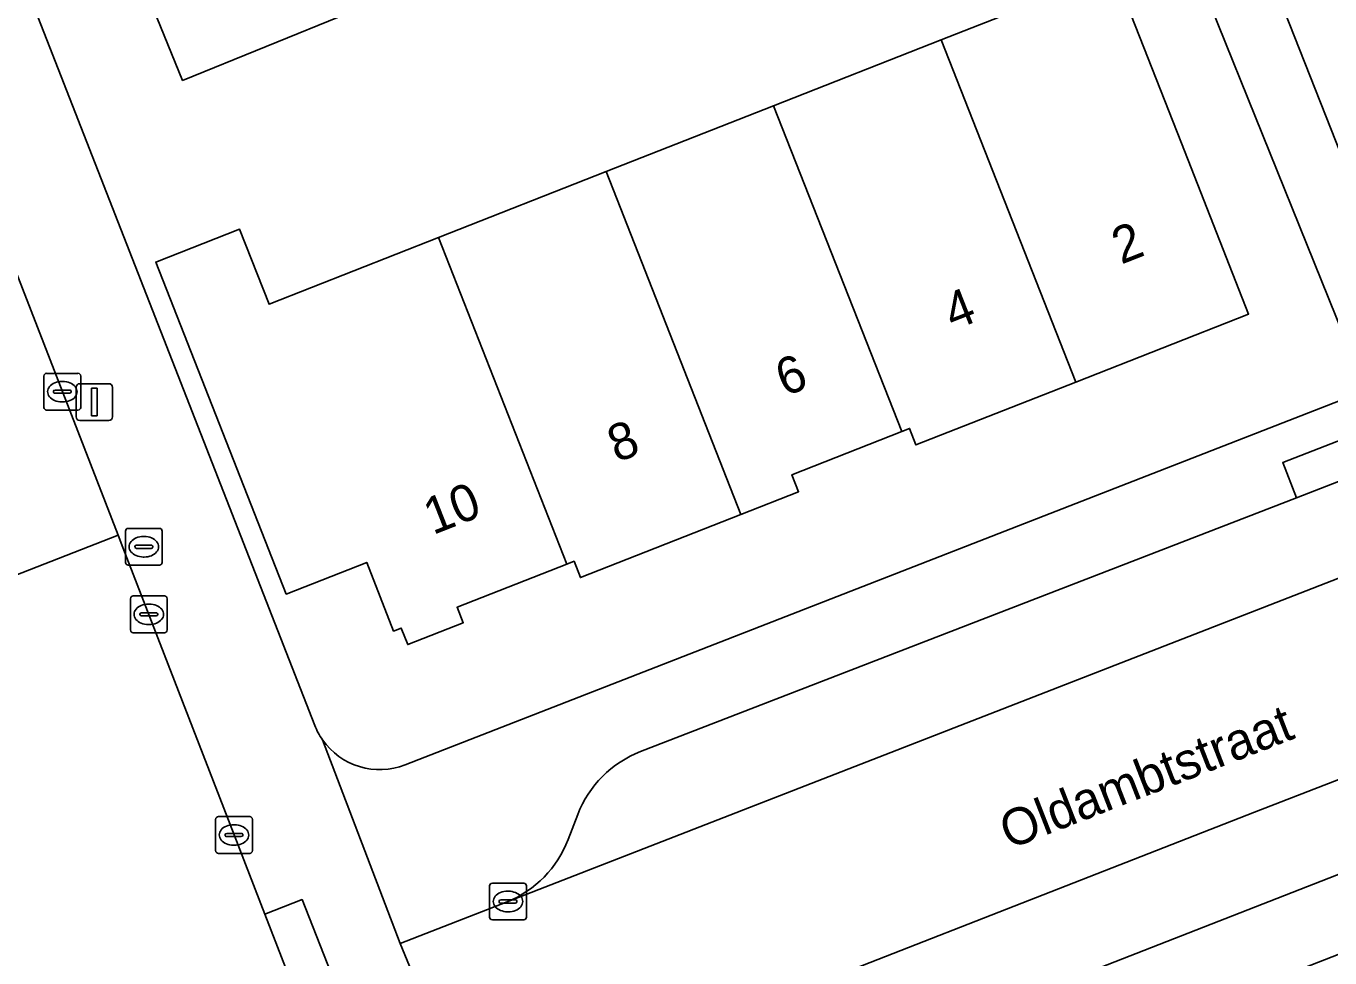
# Model space of a CAD drawing. Extents: x 159680 to 160786, y 387323 to 388340.
# Drawn here: x 159913.35 to 159948.85, y 387801.26 to 387826.64 of the extents above; entities that cross this region are included whole.
import ezdxf

# ---------------------------------------------------------------- set-up
doc = ezdxf.new("R2010")
doc.units = 0
for name, color, linetype in [('IMGEO_Brandkraan', 7, 'Continuous'), ('IMGEO_Erf', 7, 'Continuous'), ('IMGEO_Kolk', 7, 'Continuous'), ('IMGEO_Lichtmast', 7, 'Continuous'), ('IMGEO_Openbare_ruimte_label', 7, 'Continuous'), ('IMGEO_Pand', 7, 'Continuous'), ('IMGEO_Pand_nummerreeks', 7, 'Continuous'), ('IMGEO_Parkeervlak_open', 7, 'Continuous'), ('IMGEO_Rijbaan_lokaal_gesloten', 7, 'Continuous'), ('IMGEO_Rijbaan_lokaal_open', 7, 'Continuous'), ('IMGEO_Voetpad_open', 7, 'Continuous')]:
    doc.layers.add(name, color=color, linetype=linetype)

msp = doc.modelspace()

# ---------------------------------------------------------------- linework, layer by layer
at = {"layer": 'IMGEO_Brandkraan'}
for p, q in [((159916.053, 387812.033), (159916.053, 387812.885)), ((159916.128, 387812.959), (159916.98, 387812.959)), ((159917.054, 387812.885), (159917.054, 387812.033)), ((159916.541, 387812.739), (159916.566, 387812.739)), ((159916.312, 387812.453), (159916.312, 387812.465)), ((159916.75, 387812.416), (159916.352, 387812.416)), ((159916.355, 387812.502), (159916.753, 387812.502)), ((159916.564, 387812.179), (159916.539, 387812.179)), ((159916.796, 387812.465), (159916.796, 387812.453)), ((159916.98, 387811.959), (159916.128, 387811.959))]:
    msp.add_line(p, q, dxfattribs=at)
for points in [[(159916.053, 387812.033), (159916.053, 387812.885)], [(159916.128, 387812.959), (159916.98, 387812.959)], [(159917.054, 387812.885), (159917.054, 387812.033)], [(159916.98, 387811.959), (159916.128, 387811.959)]]:
    msp.add_lwpolyline(points, dxfattribs=at)
for centre, radius, start, end in [((159916.13, 387812.883), 0.0765, 91.552, 178.448), ((159916.13, 387812.883), 0.0765, 91.552, 178.448), ((159916.978, 387812.883), 0.0765, 1.552, 88.448), ((159916.978, 387812.883), 0.0765, 1.552, 88.448), ((159916.352, 387812.462), 0.0403, 85.8775, 175.7526), ((159916.349, 387812.452), 0.0366, 178.938, 274.7102), ((159916.753, 387812.459), 0.043, 264.8664, 352.4533), ((159916.757, 387812.464), 0.0386, 1.7309, 96.639), ((159916.13, 387812.035), 0.0765, 181.552, 268.448), ((159916.13, 387812.035), 0.0765, 181.552, 268.448), ((159916.978, 387812.035), 0.0765, 271.552, 358.448), ((159916.978, 387812.035), 0.0765, 271.552, 358.448)]:
    msp.add_arc(centre, radius, start, end, dxfattribs=at)
for centre, major_axis, ratio, start_param, end_param in [((159916.54, 387812.459), (-0.387, 0.002), 0.722429, 4.712389, 7.853982), ((159916.565, 387812.459), (-0.39, 0.002), 0.717154, 1.570796, 4.712389)]:
    msp.add_ellipse(centre, major_axis=major_axis, ratio=ratio, start_param=start_param, end_param=end_param, dxfattribs=at)
at = {"layer": 'IMGEO_Erf'}
for points in [[(159966.687, 387844.688), (159952.097, 387882.134), (159929.514, 387872.862), (159951.443, 387817.344), (159972.219, 387825.439)], [(159944.202, 387830.659), (159941.502, 387829.654), (159939.753, 387834.352), (159935.731, 387832.856), (159934.772, 387835.434), (159923.434, 387831.171), (159924.707, 387828.045), (159922.162, 387827.009), (159917.609, 387825.155), (159916.31, 387828.346), (159913.522, 387827.256), (159921.209, 387807.595)], [(159923.671, 387806.523), (159949.825, 387816.714), (159944.202, 387830.659)], [(159930.956, 387791.493), (159935.682, 387793.345), (159940.268, 387795.143), (159944.684, 387796.874), (159944.864, 387796.414), (159945.036, 387796.481), (159948.051, 387797.663), (159947.883, 387798.09), (159949.328, 387798.656), (159949.51, 387798.191), (159949.638, 387798.241), (159952.595, 387799.4), (159952.41, 387799.873), (159953.833, 387800.43), (159954.003, 387799.998), (159954.351, 387800.134), (159953.242, 387802.979), (159928.783, 387793.44)]]:
    msp.add_lwpolyline(points, dxfattribs=at)
msp.add_lwpolyline([(159938.267, 387826.262), (159942.97, 387828.112), (159944.804, 387823.448), (159946.634, 387818.794), (159941.93, 387816.944), (159937.577, 387815.233), (159937.402, 387815.68), (159937.188, 387815.596), (159934.2, 387814.421), (159934.382, 387813.956), (159932.807, 387813.337), (159928.442, 387811.62), (159928.267, 387812.065), (159928.068, 387811.987), (159925.085, 387810.814), (159925.251, 387810.392), (159923.738, 387809.797), (159923.562, 387810.247), (159923.355, 387810.165), (159922.621, 387812.031), (159920.432, 387811.17), (159916.878, 387820.209), (159919.159, 387821.106), (159919.962, 387819.064), (159924.573, 387820.877), (159929.138, 387822.672), (159933.702, 387824.467)], close=True, dxfattribs=at)
for centre, radius, start, end in [((159922.971, 387808.288), 1.893, 201.4763, 214.8972), ((159922.976, 387808.289), 1.898, 214.8319, 291.4852)]:
    msp.add_arc(centre, radius, start, end, dxfattribs=at)
at = {"layer": 'IMGEO_Kolk'}
for p, q in [((159913.908, 387817.181), (159914.76, 387817.181)), ((159913.833, 387816.255), (159913.833, 387817.107)), ((159914.321, 387816.961), (159914.346, 387816.961)), ((159914.834, 387817.107), (159914.834, 387816.255)), ((159914.092, 387816.675), (159914.092, 387816.687)), ((159914.53, 387816.638), (159914.132, 387816.638)), ((159914.135, 387816.724), (159914.533, 387816.724)), ((159914.576, 387816.687), (159914.576, 387816.675)), ((159914.76, 387816.181), (159913.908, 387816.181)), ((159914.344, 387816.401), (159914.319, 387816.401)), ((159916.264, 387811.12), (159917.116, 387811.12)), ((159916.189, 387810.194), (159916.189, 387811.046)), ((159916.677, 387810.9), (159916.702, 387810.9)), ((159917.19, 387811.046), (159917.19, 387810.194)), ((159916.448, 387810.614), (159916.448, 387810.626)), ((159916.886, 387810.577), (159916.488, 387810.577)), ((159916.491, 387810.663), (159916.889, 387810.663)), ((159916.932, 387810.626), (159916.932, 387810.614)), ((159917.116, 387810.12), (159916.264, 387810.12)), ((159916.7, 387810.34), (159916.675, 387810.34)), ((159918.584, 387805.112), (159919.436, 387805.112)), ((159918.509, 387804.186), (159918.509, 387805.038)), ((159918.997, 387804.892), (159919.022, 387804.892)), ((159919.51, 387805.038), (159919.51, 387804.186)), ((159918.768, 387804.606), (159918.768, 387804.618)), ((159919.206, 387804.569), (159918.808, 387804.569)), ((159918.811, 387804.655), (159919.209, 387804.655)), ((159919.252, 387804.618), (159919.252, 387804.606)), ((159919.436, 387804.112), (159918.584, 387804.112)), ((159919.02, 387804.332), (159918.995, 387804.332)), ((159926.044, 387803.301), (159926.896, 387803.301)), ((159925.969, 387802.375), (159925.969, 387803.227)), ((159926.457, 387803.081), (159926.482, 387803.081)), ((159926.97, 387803.227), (159926.97, 387802.375)), ((159926.228, 387802.795), (159926.228, 387802.807)), ((159926.666, 387802.758), (159926.268, 387802.758)), ((159926.271, 387802.844), (159926.669, 387802.844)), ((159926.712, 387802.807), (159926.712, 387802.795)), ((159926.896, 387802.301), (159926.044, 387802.301)), ((159926.48, 387802.521), (159926.455, 387802.521))]:
    msp.add_line(p, q, dxfattribs=at)
for points in [[(159913.908, 387817.181), (159914.76, 387817.181)], [(159913.833, 387816.255), (159913.833, 387817.107)], [(159914.834, 387817.107), (159914.834, 387816.255)], [(159914.76, 387816.181), (159913.908, 387816.181)], [(159916.264, 387811.12), (159917.116, 387811.12)], [(159916.189, 387810.194), (159916.189, 387811.046)], [(159917.19, 387811.046), (159917.19, 387810.194)], [(159917.116, 387810.12), (159916.264, 387810.12)], [(159918.584, 387805.112), (159919.436, 387805.112)], [(159918.509, 387804.186), (159918.509, 387805.038)], [(159919.51, 387805.038), (159919.51, 387804.186)], [(159919.436, 387804.112), (159918.584, 387804.112)], [(159926.044, 387803.301), (159926.896, 387803.301)], [(159925.969, 387802.375), (159925.969, 387803.227)], [(159926.97, 387803.227), (159926.97, 387802.375)], [(159926.896, 387802.301), (159926.044, 387802.301)]]:
    msp.add_lwpolyline(points, dxfattribs=at)
for centre, radius, start, end in [((159913.91, 387817.105), 0.0765, 91.552, 178.448), ((159913.91, 387817.105), 0.0765, 91.552, 178.448), ((159914.758, 387817.105), 0.0765, 1.552, 88.448), ((159914.758, 387817.105), 0.0765, 1.552, 88.448), ((159914.132, 387816.684), 0.0403, 85.8775, 175.7526), ((159914.129, 387816.674), 0.0366, 178.938, 274.7102), ((159914.533, 387816.681), 0.043, 264.8664, 352.4533), ((159914.537, 387816.686), 0.0386, 1.7309, 96.639), ((159913.91, 387816.257), 0.0765, 181.552, 268.448), ((159913.91, 387816.257), 0.0765, 181.552, 268.448), ((159914.758, 387816.257), 0.0765, 271.552, 358.448), ((159914.758, 387816.257), 0.0765, 271.552, 358.448), ((159916.266, 387811.044), 0.0765, 91.552, 178.448), ((159916.266, 387811.044), 0.0765, 91.552, 178.448), ((159917.114, 387811.044), 0.0765, 1.552, 88.448), ((159917.114, 387811.044), 0.0765, 1.552, 88.448), ((159916.488, 387810.623), 0.0403, 85.8775, 175.7526), ((159916.485, 387810.613), 0.0366, 178.938, 274.7102), ((159916.889, 387810.62), 0.043, 264.8664, 352.4533), ((159916.893, 387810.625), 0.0386, 1.7309, 96.639), ((159916.266, 387810.196), 0.0765, 181.552, 268.448), ((159916.266, 387810.196), 0.0765, 181.552, 268.448), ((159917.114, 387810.196), 0.0765, 271.552, 358.448), ((159917.114, 387810.196), 0.0765, 271.552, 358.448), ((159918.586, 387805.036), 0.0765, 91.552, 178.448), ((159918.586, 387805.036), 0.0765, 91.552, 178.448), ((159919.434, 387805.036), 0.0765, 1.552, 88.448), ((159919.434, 387805.036), 0.0765, 1.552, 88.448), ((159918.808, 387804.615), 0.0403, 85.8775, 175.7526), ((159918.805, 387804.605), 0.0366, 178.938, 274.7102), ((159919.209, 387804.612), 0.043, 264.8664, 352.4533), ((159919.213, 387804.617), 0.0386, 1.7309, 96.639), ((159918.586, 387804.188), 0.0765, 181.552, 268.448), ((159918.586, 387804.188), 0.0765, 181.552, 268.448), ((159919.434, 387804.188), 0.0765, 271.552, 358.448), ((159919.434, 387804.188), 0.0765, 271.552, 358.448), ((159926.046, 387803.225), 0.0765, 91.552, 178.448), ((159926.046, 387803.225), 0.0765, 91.552, 178.448), ((159926.894, 387803.225), 0.0765, 1.552, 88.448), ((159926.894, 387803.225), 0.0765, 1.552, 88.448), ((159926.268, 387802.804), 0.0403, 85.8775, 175.7526), ((159926.265, 387802.794), 0.0366, 178.938, 274.7102), ((159926.669, 387802.801), 0.043, 264.8664, 352.4533), ((159926.673, 387802.806), 0.0386, 1.7309, 96.639), ((159926.046, 387802.377), 0.0765, 181.552, 268.448), ((159926.046, 387802.377), 0.0765, 181.552, 268.448), ((159926.894, 387802.377), 0.0765, 271.552, 358.448), ((159926.894, 387802.377), 0.0765, 271.552, 358.448)]:
    msp.add_arc(centre, radius, start, end, dxfattribs=at)
for centre, major_axis, ratio, start_param, end_param in [((159914.32, 387816.681), (-0.387, 0.002), 0.722429, 4.712389, 7.853982), ((159914.345, 387816.681), (-0.39, 0.002), 0.717154, 1.570796, 4.712389), ((159916.676, 387810.62), (-0.387, 0.002), 0.722429, 4.712389, 7.853982), ((159916.701, 387810.62), (-0.39, 0.002), 0.717154, 1.570796, 4.712389), ((159918.996, 387804.612), (-0.387, 0.002), 0.722429, 4.712389, 7.853982), ((159919.021, 387804.612), (-0.39, 0.002), 0.717154, 1.570796, 4.712389), ((159926.456, 387802.801), (-0.387, 0.002), 0.722429, 4.712389, 7.853982), ((159926.481, 387802.801), (-0.39, 0.002), 0.717154, 1.570796, 4.712389)]:
    msp.add_ellipse(centre, major_axis=major_axis, ratio=ratio, start_param=start_param, end_param=end_param, dxfattribs=at)
at = {"layer": 'IMGEO_Lichtmast'}
for p, q in [((159914.709, 387815.999), (159914.709, 387816.799)), ((159914.709, 387816.799), (159914.709, 387815.999)), ((159914.809, 387816.899), (159915.599, 387816.899)), ((159915.599, 387816.899), (159914.809, 387816.899)), ((159915.699, 387816.799), (159915.699, 387815.999)), ((159915.699, 387815.999), (159915.699, 387816.799)), ((159915.599, 387815.899), (159914.809, 387815.899)), ((159914.809, 387815.899), (159915.599, 387815.899))]:
    msp.add_line(p, q, dxfattribs=at)
msp.add_lwpolyline([(159915.129, 387816.774), (159915.279, 387816.774), (159915.279, 387816.024), (159915.129, 387816.024), (159915.129, 387816.774)], dxfattribs=at)
for centre, start, end in [((159914.809, 387816.799), 90, 180), ((159914.809, 387816.799), 90, 180), ((159915.599, 387816.799), 0, 90), ((159915.599, 387816.799), 360, 90), ((159914.809, 387815.999), 180, 270), ((159914.809, 387815.999), 180, 270), ((159915.599, 387815.999), 270, 0), ((159915.599, 387815.999), 270, 0)]:
    msp.add_arc(centre, 0.1, start, end, dxfattribs=at)
at = {"layer": 'IMGEO_Pand'}
for points in [[(159920.902, 387830.216), (159916.31, 387828.346), (159917.609, 387825.155), (159922.162, 387827.009)], [(159941.93, 387816.944), (159946.634, 387818.794), (159944.804, 387823.448), (159942.97, 387828.112), (159938.267, 387826.262)], [(159938.267, 387826.262), (159933.702, 387824.467), (159937.188, 387815.596), (159937.402, 387815.68), (159937.577, 387815.233), (159941.93, 387816.944)], [(159933.702, 387824.467), (159929.138, 387822.672), (159932.807, 387813.337), (159934.382, 387813.956), (159934.2, 387814.421), (159937.188, 387815.596)], [(159928.068, 387811.987), (159928.267, 387812.065), (159928.442, 387811.62), (159932.807, 387813.337), (159929.138, 387822.672), (159924.573, 387820.877)], [(159924.573, 387820.877), (159919.962, 387819.064), (159919.159, 387821.106), (159916.878, 387820.209), (159920.432, 387811.17), (159922.621, 387812.031), (159923.355, 387810.165), (159923.562, 387810.247), (159923.738, 387809.797), (159925.251, 387810.392), (159925.085, 387810.814), (159928.068, 387811.987)]]:
    msp.add_lwpolyline(points, close=True, dxfattribs=at)
at = {"layer": 'IMGEO_Parkeervlak_open'}
for points in [[(159966.707, 387821.058), (159951.326, 387815.106), (159947.936, 387813.795), (159930.079, 387806.885)], [(159926.446, 387802.791), (159949.224, 387811.657), (159970.967, 387820.07)], [(159972.771, 387815.3), (159946.794, 387805.237), (159929.996, 387798.667)], [(159934.755, 387797.935), (159969.917, 387811.687)], [(159928.368, 387805.17), (159928.104, 387804.485)]]:
    msp.add_lwpolyline(points, dxfattribs=at)
for centre, start, end in [((159931.168, 387804.088), 111.266, 158.8678), ((159925.305, 387805.566), 292.3524, 338.8782)]:
    msp.add_arc(centre, 3.001, start, end, dxfattribs=at)
at = {"layer": 'IMGEO_Rijbaan_lokaal_gesloten'}
msp.add_lwpolyline([(159911.857, 387804.088), (159909.597, 387810.335), (159915.853, 387812.774), (159911.972, 387822.765)], dxfattribs=at)
at = {"layer": 'IMGEO_Rijbaan_lokaal_open'}
for points in [[(159972.771, 387815.3), (159974.926, 387816.135), (159976.607, 387816.786), (159974.995, 387821.629), (159970.967, 387820.07), (159949.224, 387811.657), (159926.446, 387802.791), (159923.532, 387801.657), (159925.493, 387796.906), (159929.996, 387798.667), (159946.794, 387805.237)], [(159919.846, 387802.456), (159919.01, 387804.612), (159915.983, 387812.438), (159915.853, 387812.774), (159909.597, 387810.335), (159911.857, 387804.088), (159912.558, 387802.402), (159914.429, 387797.56), (159919.835, 387783.57), (159921.528, 387779.204), (159927.881, 387781.717), (159926.227, 387785.997), (159923.212, 387793.775)]]:
    msp.add_lwpolyline(points, close=True, dxfattribs=at)
at = {"layer": 'IMGEO_Voetpad_open'}
for points in [[(159888.928, 387881.56), (159894.152, 387868.64), (159895.931, 387864.06), (159896.928, 387864.448), (159898.216, 387861.134), (159897.219, 387860.746), (159906.532, 387836.771), (159907.513, 387834.245), (159910.633, 387826.211), (159911.615, 387826.638), (159912.965, 387823.164), (159911.972, 387822.765), (159915.853, 387812.774), (159915.983, 387812.438), (159919.01, 387804.612), (159919.846, 387802.456), (159920.861, 387802.854), (159924.268, 387794.188), (159923.212, 387793.775), (159926.227, 387785.997)], [(159921.209, 387807.595), (159913.522, 387827.256), (159912.952, 387828.714), (159900.404, 387860.81), (159899.864, 387862.192), (159898.601, 387865.422), (159892.901, 387880.003)], [(159944.202, 387830.659), (159949.825, 387816.714), (159951.443, 387817.344), (159929.514, 387872.862)], [(159972.219, 387825.439), (159951.443, 387817.344), (159949.825, 387816.714), (159923.671, 387806.523)], [(159930.079, 387806.885), (159947.936, 387813.795), (159947.564, 387814.756), (159950.954, 387816.067), (159951.326, 387815.106), (159966.707, 387821.058)], [(159969.917, 387811.687), (159934.755, 387797.935)], [(159921.418, 387807.205), (159923.532, 387801.657), (159926.446, 387802.791)], [(159927.592, 387791.332), (159925.493, 387796.906), (159923.532, 387801.657), (159921.418, 387807.205)], [(159928.104, 387804.485), (159928.368, 387805.17)], [(159928.783, 387793.44), (159953.242, 387802.979)]]:
    msp.add_lwpolyline(points, dxfattribs=at)
for points in [[(159951.326, 387815.106), (159950.954, 387816.067), (159947.564, 387814.756), (159947.936, 387813.795)], [(159920.861, 387802.854), (159919.846, 387802.456), (159923.212, 387793.775), (159924.268, 387794.188)]]:
    msp.add_lwpolyline(points, close=True, dxfattribs=at)
for centre, radius, start, end in [((159922.971, 387808.288), 1.893, 201.4763, 214.8972), ((159922.976, 387808.289), 1.898, 214.8319, 291.4852), ((159931.168, 387804.088), 3.001, 111.266, 158.8678), ((159925.305, 387805.566), 3.001, 292.3524, 338.8782)]:
    msp.add_arc(centre, radius, start, end, dxfattribs=at)

# ---------------------------------------------------------------- texts
at = {"layer": 'IMGEO_Openbare_ruimte_label'}
msp.add_text('Oldambtstraat', height=1, rotation=21.2802, dxfattribs=at).set_placement((159940.11, 387804.212))
at = {"layer": 'IMGEO_Pand_nummerreeks'}
for s, p in [('2', (159943.164, 387820.138)), ('4', (159938.587, 387818.34)), ('6', (159934.007, 387816.541)), ('8', (159929.432, 387814.742)), ('10', (159924.424, 387812.774))]:
    msp.add_text(s, height=1, rotation=21.4524, dxfattribs=at).set_placement(p)

doc.saveas('drawing.dxf')
